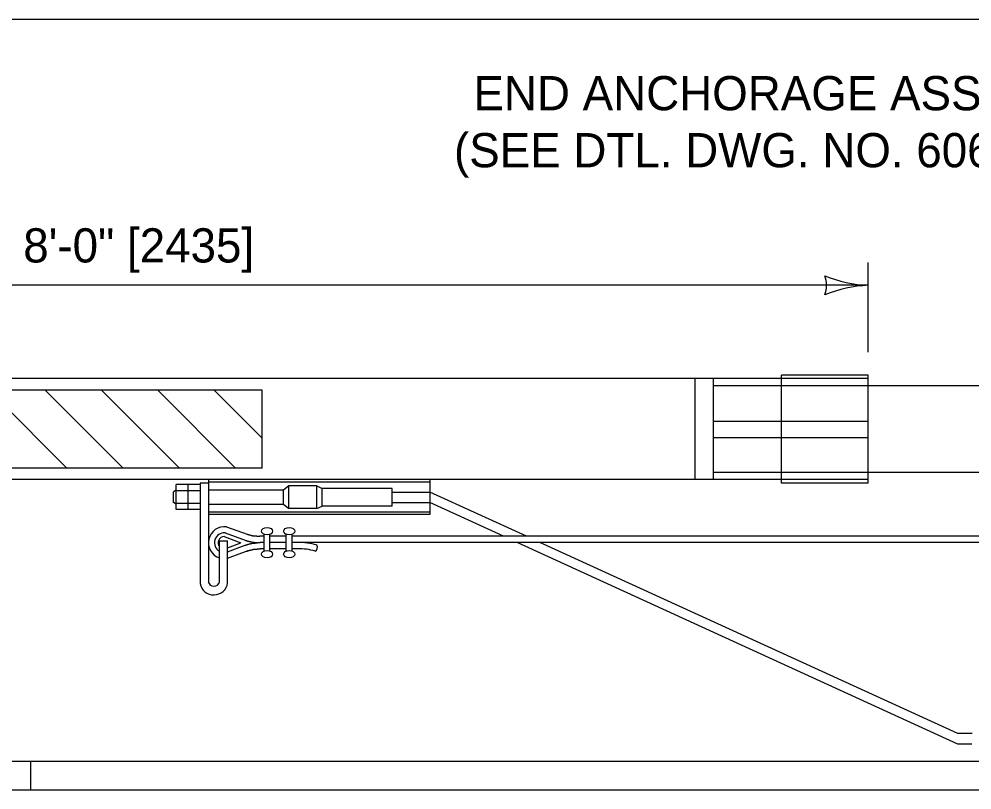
# Model space of a CAD drawing. Extents: x 49991.4 to 50021, y 49987.6 to 50011.4.
# Drawn here: x 50014.114 to 50015.787, y 49994.335 to 49995.687 of the extents above; entities that cross this region are included whole.
import ezdxf

# ---------------------------------------------------------------- set-up
doc = ezdxf.new("R2010")
doc.units = 0
for name, color, linetype in [('Level 1', 7, 'Continuous'), ('Level 2', 7, 'Continuous'), ('Level 3', 7, 'Continuous'), ('Level 4', 7, 'Continuous'), ('Level 5', 7, 'Continuous'), ('Level 6', 7, 'Continuous')]:
    doc.layers.add(name, color=color, linetype=linetype)

msp = doc.modelspace()

# ---------------------------------------------------------------- linework, layer by layer
at = {"layer": 'Level 1'}
for p, q in [((50015.4527, 49995.0567), (50013.2309, 49995.0567)), ((50015.4527, 49994.8733), (50015.4527, 49995.0628)), ((50015.6047, 49995.0628), (50015.4527, 49995.0628)), ((50015.6047, 49994.8733), (50015.6047, 49995.0628)), ((50016.2122, 49995.044), (50015.6047, 49995.044)), ((50015.8249, 49994.892), (50015.6047, 49994.892)), ((50015.4527, 49994.8794), (50013.2309, 49994.8794)), ((50014.4323, 49994.8706), (50014.3901, 49994.8706)), ((50014.3901, 49994.8267), (50014.3901, 49994.8706)), ((50014.4112, 49994.8267), (50014.4112, 49994.8706)), ((50014.4323, 49994.8732), (50014.4323, 49994.6974)), ((50014.4466, 49994.8793), (50014.4466, 49994.7001)), ((50014.8353, 49994.8793), (50014.8353, 49994.8179)), ((50015.6047, 49994.8733), (50015.4527, 49994.8733)), ((50014.3901, 49994.8609), (50014.3855, 49994.8579)), ((50014.3855, 49994.8393), (50014.3855, 49994.8579)), ((50014.3901, 49994.8363), (50014.3901, 49994.8609)), ((50014.4323, 49994.8597), (50014.3901, 49994.8597)), ((50015.0049, 49994.7801), (50014.8353, 49994.8576)), ((50014.3901, 49994.8363), (50014.3855, 49994.8393)), ((50014.4323, 49994.8376), (50014.3901, 49994.8376)), ((50014.9647, 49994.7801), (50014.8353, 49994.8393)), ((50014.4323, 49994.8267), (50014.3901, 49994.8267)), ((50014.8353, 49994.8179), (50014.4466, 49994.8179)), ((50014.4759, 49994.7861), (50014.5111, 49994.773)), ((50014.4783, 49994.7966), (50014.5148, 49994.7836)), ((50014.5446, 49994.754), (50014.5446, 49994.7835)), ((50014.5545, 49994.754), (50014.5545, 49994.7838)), ((50014.5834, 49994.754), (50014.5834, 49994.7834)), ((50014.5935, 49994.754), (50014.5935, 49994.7833)), ((50014.4662, 49994.7718), (50014.4805, 49994.7718)), ((50014.4662, 49994.7001), (50014.4662, 49994.7718)), ((50014.4741, 49994.7796), (50014.5039, 49994.7686)), ((50014.4805, 49994.6981), (50014.4805, 49994.7718)), ((50014.4805, 49994.7597), (50014.5039, 49994.7686)), ((50014.5446, 49994.7801), (50014.5367, 49994.7801)), ((50014.5446, 49994.7688), (50014.5374, 49994.7688)), ((50014.5834, 49994.7801), (50014.5545, 49994.7801)), ((50014.5834, 49994.7688), (50014.5545, 49994.7688)), ((50016.0568, 49994.7801), (50014.5935, 49994.7801)), ((50016.0575, 49994.7692), (50014.5935, 49994.7692)), ((50015.762, 49994.4155), (50014.9885, 49994.7692)), ((50015.762, 49994.4338), (50015.0286, 49994.7692)), ((50014.4805, 49994.7529), (50014.5111, 49994.7644)), ((50014.4805, 49994.7417), (50014.5166, 49994.7549)), ((50014.5446, 49994.7579), (50014.5367, 49994.7579)), ((50014.5834, 49994.7579), (50014.5545, 49994.7579)), ((50014.6036, 49994.7579), (50014.5935, 49994.7579)), ((50015.7869, 49994.4338), (50015.762, 49994.4338)), ((50015.7864, 49994.4155), (50015.762, 49994.4155)), ((50013.972, 49994.3852), (50015.9656, 49994.3852)), ((50014.1352, 49994.335), (50014.1352, 49994.3852)), ((49999.9212, 49994.335), (50016.2933, 49994.335))]:
    msp.add_line(p, q, dxfattribs=at)
msp.add_lwpolyline([(50014.4466, 49994.8732), (50014.4323, 49994.8732)], dxfattribs=at)
for centre, radius, start, end in [((50014.4748, 49994.7687), 0.028, 82.8848, 252.1314), ((50014.4748, 49994.7687), 0.0174, 86.3788, 240.4211), ((50014.4748, 49994.7687), 0.0109, 93.5506, 217.9772), ((50014.6075, 49994.6704), 0.0985, 72.3633, 92.486), ((50014.6075, 49994.6703), 0.0876, 72.3419, 92.486), ((50014.6295, 49994.7609), 0.00844, 302.3935, 22.8977), ((50014.4564, 49994.7023), 0.0101, 192.9921, 346.8397), ((50014.4563, 49994.7015), 0.0244, 189.7483, 352.0529)]:
    msp.add_arc(centre, radius, start, end, dxfattribs=at)
for centre in [(50014.5496, 49994.7889), (50014.5885, 49994.7889), (50014.5496, 49994.7485), (50014.5885, 49994.7485)]:
    msp.add_ellipse(centre, major_axis=(0.00987, 0), ratio=0.660302, dxfattribs=at)
for points in [[(50014.5148, 49994.7836), (50014.5154, 49994.7834), (50014.5159, 49994.7834), (50014.5163, 49994.7832), (50014.5168, 49994.783), (50014.5172, 49994.783), (50014.5176, 49994.7827), (50014.518, 49994.7827), (50014.5184, 49994.7827), (50014.5189, 49994.7825), (50014.5195, 49994.7825), (50014.5197, 49994.7823), (50014.5202, 49994.7823), (50014.5208, 49994.7821), (50014.5213, 49994.7819), (50014.5215, 49994.7819), (50014.5219, 49994.7816), (50014.5226, 49994.7814), (50014.523, 49994.7814), (50014.5234, 49994.7812), (50014.5237, 49994.7812), (50014.5243, 49994.781), (50014.5248, 49994.781), (50014.5252, 49994.781), (50014.5256, 49994.781), (50014.5261, 49994.781), (50014.5267, 49994.781), (50014.5269, 49994.7808), (50014.5274, 49994.7808), (50014.5278, 49994.7808), (50014.5285, 49994.7808), (50014.5289, 49994.7808), (50014.5293, 49994.7808), (50014.5298, 49994.7806), (50014.5302, 49994.7806), (50014.5306, 49994.7806), (50014.5311, 49994.7806), (50014.5315, 49994.7803), (50014.5322, 49994.7803), (50014.5324, 49994.7803), (50014.533, 49994.7803), (50014.5334, 49994.7803), (50014.5338, 49994.7803), (50014.5343, 49994.7801), (50014.5347, 49994.7801), (50014.5352, 49994.7801), (50014.5356, 49994.7801), (50014.536, 49994.7801), (50014.5367, 49994.7801)], [(50014.5111, 49994.773), (50014.5118, 49994.7728), (50014.5122, 49994.7726), (50014.5127, 49994.7726), (50014.5133, 49994.7726), (50014.5137, 49994.7724), (50014.5144, 49994.7722), (50014.5148, 49994.772), (50014.5153, 49994.7717), (50014.5157, 49994.7715), (50014.5164, 49994.7713), (50014.517, 49994.7713), (50014.5172, 49994.7711), (50014.5179, 49994.7711), (50014.5183, 49994.7711), (50014.5187, 49994.7709), (50014.5193, 49994.7706), (50014.52, 49994.7706), (50014.5204, 49994.7706), (50014.5209, 49994.7704), (50014.5215, 49994.7704), (50014.522, 49994.7702), (50014.5224, 49994.77), (50014.5231, 49994.7698), (50014.5235, 49994.7698), (50014.5241, 49994.7696), (50014.5246, 49994.7696), (50014.525, 49994.7696), (50014.5257, 49994.7696), (50014.5261, 49994.7696), (50014.5265, 49994.7696), (50014.5272, 49994.7693), (50014.5279, 49994.7693), (50014.5281, 49994.7693), (50014.5287, 49994.7691), (50014.5294, 49994.7691), (50014.5298, 49994.7691), (50014.5303, 49994.7689), (50014.5311, 49994.7689), (50014.5313, 49994.7689), (50014.532, 49994.7687), (50014.5327, 49994.7687), (50014.5328, 49994.7687)], [(50014.5111, 49994.7644), (50014.5118, 49994.7646), (50014.5122, 49994.7646), (50014.5127, 49994.7649), (50014.5133, 49994.7649), (50014.5137, 49994.7651), (50014.5144, 49994.7653), (50014.5148, 49994.7655), (50014.5153, 49994.7657), (50014.5157, 49994.7657), (50014.5164, 49994.7659), (50014.517, 49994.7662), (50014.5172, 49994.7662), (50014.5179, 49994.7664), (50014.5183, 49994.7664), (50014.5187, 49994.7666), (50014.5193, 49994.7666), (50014.52, 49994.7668), (50014.5204, 49994.7668), (50014.5209, 49994.767), (50014.5215, 49994.767), (50014.522, 49994.7673), (50014.5224, 49994.7675), (50014.5231, 49994.7675), (50014.5235, 49994.7677), (50014.5241, 49994.7677), (50014.5246, 49994.7679), (50014.525, 49994.7679), (50014.5257, 49994.7679), (50014.5261, 49994.7679), (50014.5265, 49994.7679), (50014.5272, 49994.7679), (50014.5279, 49994.7681), (50014.5281, 49994.7681), (50014.5287, 49994.7681), (50014.5294, 49994.7683), (50014.5298, 49994.7683), (50014.5303, 49994.7683), (50014.5311, 49994.7686), (50014.5313, 49994.7686), (50014.532, 49994.7686), (50014.5327, 49994.7686), (50014.5329, 49994.7688), (50014.5337, 49994.7688), (50014.5341, 49994.7688), (50014.5345, 49994.7688), (50014.535, 49994.7688), (50014.5359, 49994.7688), (50014.5363, 49994.7688), (50014.5365, 49994.7688), (50014.5374, 49994.7688)], [(50014.514, 49994.7538), (50014.5144, 49994.7538), (50014.5148, 49994.7538), (50014.5153, 49994.754), (50014.5155, 49994.7542), (50014.5161, 49994.7545), (50014.5166, 49994.7547), (50014.517, 49994.7549), (50014.5175, 49994.7551), (50014.5179, 49994.7551), (50014.5183, 49994.7551), (50014.5187, 49994.7553), (50014.5191, 49994.7553), (50014.5196, 49994.7555), (50014.5202, 49994.7555), (50014.5204, 49994.7555), (50014.5209, 49994.7558), (50014.5215, 49994.756), (50014.522, 49994.756), (50014.5222, 49994.7562), (50014.5226, 49994.7564), (50014.5233, 49994.7564), (50014.5237, 49994.7566), (50014.5241, 49994.7566), (50014.5244, 49994.7569), (50014.525, 49994.7569), (50014.5255, 49994.7571), (50014.5259, 49994.7571), (50014.5263, 49994.7571), (50014.5268, 49994.7571), (50014.5274, 49994.7571), (50014.5276, 49994.7571), (50014.5281, 49994.7573), (50014.5285, 49994.7573), (50014.5292, 49994.7573), (50014.5296, 49994.7573), (50014.53, 49994.7573), (50014.5305, 49994.7573), (50014.5309, 49994.7575), (50014.5313, 49994.7575), (50014.5318, 49994.7575), (50014.5322, 49994.7575), (50014.5329, 49994.7577), (50014.5331, 49994.7577), (50014.5337, 49994.7577), (50014.5341, 49994.7577), (50014.5345, 49994.7577), (50014.535, 49994.7577), (50014.5354, 49994.7577), (50014.5359, 49994.7577), (50014.5363, 49994.7577), (50014.5367, 49994.7579), (50014.5374, 49994.7579)]]:
    msp.add_spline(points, degree=3, dxfattribs=at)
at = {"layer": 'Level 3'}
for p, q in [((50015.6047, 49995.1028), (50015.6047, 49995.2602)), ((50015.6047, 49995.2202), (50013.1739, 49995.2202))]:
    msp.add_line(p, q, dxfattribs=at)
for centre, radius, start, end in [((50015.6139, 49995.4423), 0.2223, 247.456, 267.6395), ((50015.4765, 49995.2202), 0.0548, 342.1388, 17.8612), ((50015.6162, 49994.9875), 0.233, 92.8273, 112.0772)]:
    msp.add_arc(centre, radius, start, end, dxfattribs=at)
at = {"layer": 'Level 4'}
for p, q in [((50015.3008, 49994.8794), (50015.3008, 49995.0567)), ((50015.3329, 49994.8794), (50015.3329, 49995.0567)), ((50015.6047, 49995.0567), (50015.4527, 49995.0567)), ((50014.5412, 49995.0363), (50012.7392, 49995.0363)), ((50014.5412, 49994.8996), (50014.5412, 49995.0363)), ((50015.6047, 49995.044), (50015.3329, 49995.044)), ((50015.6047, 49994.9813), (50015.3329, 49994.9813)), ((50015.6047, 49994.9528), (50015.3329, 49994.9528)), ((50014.5412, 49994.8996), (50012.7392, 49994.8996)), ((50015.6047, 49994.892), (50015.3329, 49994.892)), ((50014.8353, 49994.8747), (50014.4466, 49994.8747)), ((50014.5878, 49994.8686), (50014.5786, 49994.8609)), ((50014.6369, 49994.8686), (50014.5878, 49994.8686)), ((50014.5878, 49994.8286), (50014.5878, 49994.8686)), ((50014.6369, 49994.8686), (50014.6462, 49994.8638)), ((50014.6369, 49994.8286), (50014.6369, 49994.8686)), ((50015.6047, 49994.8794), (50015.4527, 49994.8794)), ((50014.5786, 49994.8609), (50014.4466, 49994.8609)), ((50014.5786, 49994.8363), (50014.5786, 49994.8609)), ((50014.6462, 49994.833), (50014.6462, 49994.8638)), ((50014.7691, 49994.8638), (50014.6462, 49994.8638)), ((50014.7691, 49994.833), (50014.7691, 49994.8638)), ((50014.7691, 49994.8576), (50014.8353, 49994.8576)), ((50014.4466, 49994.8363), (50014.5786, 49994.8363)), ((50014.5786, 49994.8363), (50014.5878, 49994.8286)), ((50014.7696, 49994.8393), (50014.8353, 49994.8393)), ((50014.8353, 49994.8225), (50014.4466, 49994.8225)), ((50014.6369, 49994.8286), (50014.5878, 49994.8286)), ((50014.6369, 49994.8286), (50014.6462, 49994.833)), ((50014.7691, 49994.833), (50014.6462, 49994.833))]:
    msp.add_line(p, q, dxfattribs=at)
at = {"layer": 'Level 5'}
for p, q in [((50014.1982, 49994.8996), (50014.0615, 49995.0363)), ((50014.2969, 49994.8996), (50014.1603, 49995.0363)), ((50014.3959, 49994.8996), (50014.2591, 49995.0363)), ((50014.4945, 49994.8996), (50014.358, 49995.0363)), ((50014.5412, 49994.952), (50014.4568, 49995.0363))]:
    msp.add_line(p, q, dxfattribs=at)
at = {"layer": 'Level 6'}
msp.add_lwpolyline([(50013.832, 49995.3202), (50013.832, 49995.6872), (50016.4251, 49995.6872)], dxfattribs=at)

# ---------------------------------------------------------------- texts
at = {"layer": 'Level 2'}
for s, p in [('END ANCHORAGE ASSEMBLY', (50014.9118, 49995.5272)), ('(SEE DTL. DWG. NO. 606-56A)', (50014.8777, 49995.4272)), ('8\'-0" [2435]', (50014.1218, 49995.2602))]:
    msp.add_text(s, height=0.06, dxfattribs=at).set_placement(p)

doc.saveas('drawing.dxf')
